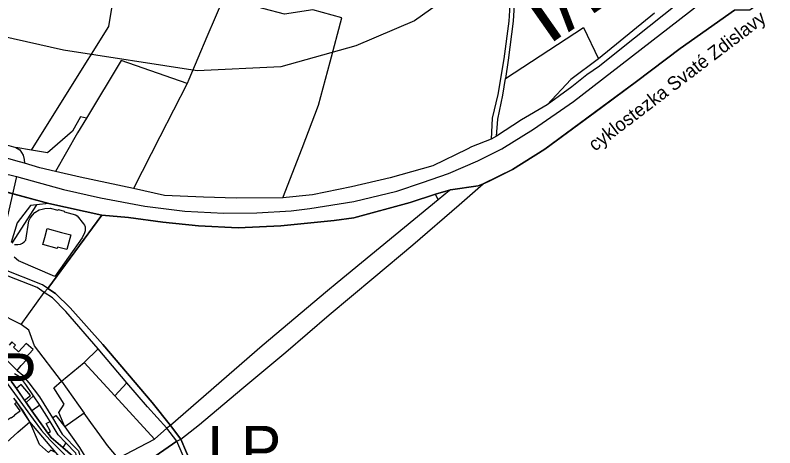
# Model space of a CAD drawing. Extents: x -706771 to -698463, y -971709 to -967107.
# Drawn here: x -701879 to -701207, y -969372 to -968988 of the extents above; entities that cross this region are included whole.
import ezdxf

# ---------------------------------------------------------------- set-up
doc = ezdxf.new("R2010")
doc.units = 0
for name, color, linetype in [('_hranice krajinny raz ochrana chrakteru zástavby KR2', 7, 'Continuous'), ('_KRAJINNY CELEK', 7, 'Continuous'), ('_KRAJINNY OKRSEK', 7, 'Continuous'), ('KN_Hranice_parcel', 7, 'Continuous'), ('Komunikace I třídy osy S', 7, 'Continuous'), ('Komunikace III třídy osy S', 7, 'Continuous'), ('Komunikace popis trid a kategorie popis S N', 7, 'Continuous'), ('Koridor uzemni rezervy zeleznicni trat - osa N', 7, 'Continuous'), ('Prvky nelesni zeleně vhodné k zařazení do vyšší ochrany_popis N', 7, 'Continuous'), ('Prvky nelesní zeleně _dominantní prvky solitérní', 7, 'Continuous'), ('Trasy cyklo popis N', 7, 'Continuous'), ('Trasy cykloturistické N', 7, 'Continuous'), ('Trasy cykloturistické S', 7, 'Continuous'), ('Trasy turistické S', 7, 'Continuous')]:
    doc.layers.add(name, color=color, linetype=linetype)

msp = doc.modelspace()

# ---------------------------------------------------------------- linework, layer by layer
at = {"layer": '_hranice krajinny raz ochrana chrakteru zástavby KR2'}
for p, q in [((-701849.34, -969155.36), (-701907.69, -969139.6)), ((-701802.49, -969165.64), (-701849.34, -969155.36)), ((-701850.32, -969230.41), (-701802.49, -969165.64)), ((-701843.4, -969234.95), (-701850.32, -969230.41)), ((-701757.91, -969331.37), (-701801.62, -969280.03)), ((-701741.49, -969351.93), (-701757.91, -969331.37)), ((-701732.44, -969363.94), (-701741.49, -969351.93)), ((-701691.82, -969459.3), (-701732.44, -969363.94))]:
    msp.add_line(p, q, dxfattribs=at)
msp.add_lwpolyline([(-701801.62, -969280.03), (-701830.6, -969247.76), (-701843.4, -969234.95)], dxfattribs=at)
at = {"layer": '_KRAJINNY CELEK'}
for p, q in [((-701410.21, -969107.23), (-701438.74, -969125.05)), ((-701438.74, -969125.05), (-701464.83, -969137.71)), ((-701493.74, -969143), (-701507.04, -969146.86)), ((-701507.04, -969146.86), (-701529.34, -969154.45)), ((-701529.34, -969154.45), (-701579.3, -969167.87)), ((-701850.32, -969230.41), (-701843.4, -969234.95)), ((-701843.4, -969234.95), (-701830.6, -969247.76)), ((-701830.6, -969247.76), (-701801.62, -969280.03)), ((-701801.62, -969280.03), (-701757.91, -969331.37)), ((-701757.91, -969331.37), (-701741.49, -969351.93)), ((-701741.49, -969351.93), (-701732.44, -969363.94)), ((-701732.44, -969363.94), (-701691.82, -969459.3))]:
    msp.add_line(p, q, dxfattribs=at)
for points in [[(-701438.74, -969125.05), (-701410.21, -969107.23), (-701329.09, -969047.29), (-701290.25, -969018.1), (-701242.42, -968984.02), (-701228.7, -968983.67), (-701152.68, -968925.93), (-701062.83, -968856.76), (-701034.31, -968835.32), (-700968.07, -968795.14), (-700866.46, -968735.36), (-700819.27, -968707.39), (-700809.62, -968702.94)], [(-701228.7, -968983.67), (-701242.42, -968984.02), (-701290.25, -969018.1)], [(-701290.25, -969018.1), (-701329.09, -969047.29), (-701410.21, -969107.23)], [(-701850.32, -969230.41), (-701802.49, -969165.64), (-701778.72, -969167.57), (-701748.57, -969171.91), (-701716.87, -969174.94), (-701681.68, -969176.94), (-701643.83, -969175.03), (-701596.73, -969170.18), (-701579.3, -969167.87), (-701529.34, -969154.45), (-701507.04, -969146.86), (-701493.74, -969143), (-701469.25, -969139.46), (-701464.83, -969137.71), (-701438.74, -969125.05)], [(-701464.83, -969137.71), (-701469.25, -969139.46), (-701493.74, -969143)], [(-701716.87, -969174.94), (-701748.57, -969171.91), (-701778.72, -969167.57), (-701802.49, -969165.64), (-701850.32, -969230.41)], [(-701579.3, -969167.87), (-701596.73, -969170.18), (-701643.83, -969175.03), (-701681.68, -969176.94), (-701716.87, -969174.94)], [(-701691.82, -969459.3), (-701732.44, -969363.94), (-701741.49, -969351.93), (-701757.91, -969331.37), (-701801.62, -969280.03), (-701830.6, -969247.76), (-701843.4, -969234.95), (-701850.32, -969230.41)]]:
    msp.add_lwpolyline(points, dxfattribs=at)
at = {"layer": '_KRAJINNY OKRSEK'}
for p, q in [((-701290.25, -969018.1), (-701329.09, -969047.29)), ((-701329.09, -969047.29), (-701410.21, -969107.23)), ((-701438.74, -969125.05), (-701410.21, -969107.23)), ((-701410.21, -969107.23), (-701438.74, -969125.05)), ((-701464.83, -969137.71), (-701438.74, -969125.05)), ((-701438.74, -969125.05), (-701464.83, -969137.71)), ((-701507.04, -969146.86), (-701493.74, -969143)), ((-701493.74, -969143), (-701507.04, -969146.86)), ((-701493.74, -969143), (-701469.25, -969139.46)), ((-701469.25, -969139.46), (-701493.74, -969143)), ((-701469.25, -969139.46), (-701464.83, -969137.71)), ((-701464.83, -969137.71), (-701469.25, -969139.46)), ((-701529.34, -969154.45), (-701507.04, -969146.86)), ((-701507.04, -969146.86), (-701529.34, -969154.45)), ((-701529.34, -969154.45), (-701579.3, -969167.87)), ((-701802.49, -969165.64), (-701850.32, -969230.41)), ((-701850.32, -969230.41), (-701802.49, -969165.64)), ((-701850.32, -969230.41), (-701843.4, -969234.95)), ((-701843.4, -969234.95), (-701850.32, -969230.41)), ((-701801.62, -969280.03), (-701757.91, -969331.37)), ((-701757.91, -969331.37), (-701801.62, -969280.03)), ((-701757.91, -969331.37), (-701741.49, -969351.93)), ((-701741.49, -969351.93), (-701757.91, -969331.37)), ((-701741.49, -969351.93), (-701732.44, -969363.94)), ((-701732.44, -969363.94), (-701741.49, -969351.93)), ((-701732.44, -969363.94), (-701691.82, -969459.3)), ((-701691.82, -969459.3), (-701732.44, -969363.94))]:
    msp.add_line(p, q, dxfattribs=at)
for points in [[(-701290.25, -969018.1), (-701242.42, -968984.02), (-701228.7, -968983.67), (-701152.68, -968925.93)], [(-701228.7, -968983.67), (-701242.42, -968984.02), (-701290.25, -969018.1)], [(-702372.57, -969017.37), (-702327.41, -969029), (-702270.92, -969043.45), (-702200.53, -969061.14), (-702152.82, -969073.6), (-702124.76, -969080.25), (-702083.33, -969089.48), (-702078.54, -969090.62), (-702054.63, -969097.31), (-702050.66, -969098.08), (-702026.91, -969104.4), (-701983.39, -969123.44), (-701955.32, -969129.82), (-701953.31, -969128.2), (-701949.94, -969127.84), (-701933.2, -969133.88), (-701926.94, -969135.13), (-701907.69, -969139.6), (-701849.34, -969155.36), (-701802.49, -969165.64)], [(-701410.21, -969107.23), (-701329.09, -969047.29), (-701290.25, -969018.1)], [(-701802.49, -969165.64), (-701849.34, -969155.36), (-701907.69, -969139.6)], [(-701596.73, -969170.18), (-701579.3, -969167.87), (-701529.34, -969154.45)], [(-701802.49, -969165.64), (-701778.72, -969167.57), (-701748.57, -969171.91), (-701716.87, -969174.94)], [(-701716.87, -969174.94), (-701748.57, -969171.91), (-701778.72, -969167.57), (-701802.49, -969165.64)], [(-701579.3, -969167.87), (-701596.73, -969170.18), (-701643.83, -969175.03)], [(-701716.87, -969174.94), (-701681.68, -969176.94), (-701643.83, -969175.03), (-701596.73, -969170.18)], [(-701643.83, -969175.03), (-701681.68, -969176.94), (-701716.87, -969174.94)], [(-701843.4, -969234.95), (-701830.6, -969247.76), (-701801.62, -969280.03)], [(-701801.62, -969280.03), (-701830.6, -969247.76), (-701843.4, -969234.95)]]:
    msp.add_lwpolyline(points, dxfattribs=at)
at = {"layer": 'KN_Hranice_parcel'}
for p, q in [((-701313.15, -968986.53), (-701362.78, -969027.22)), ((-701452.9, -969095.61), (-701457.68, -969098.23)), ((-701864.64, -969107.96), (-701878.62, -969105.54)), ((-701849.34, -969155.36), (-701905.57, -969140.09)), ((-701507.04, -969146.86), (-701493.74, -969143)), ((-701504.72, -969151.85), (-701507.04, -969146.86)), ((-701860.42, -969156.4), (-701882.03, -969190.42)), ((-701849.34, -969155.36), (-701860.42, -969156.4)), ((-701802.49, -969165.64), (-701849.34, -969155.36)), ((-701850.32, -969230.41), (-701802.49, -969165.64)), ((-701853.36, -969233.93), (-701850.32, -969230.41)), ((-701873.85, -969262.27), (-701853.36, -969233.93)), ((-701873.85, -969262.27), (-701901, -969248.61)), ((-701805.59, -969283.84), (-701818.22, -969295.98)), ((-701780.28, -969314.21), (-701805.59, -969283.84)), ((-701892.82, -969288.08), (-701877.53, -969303.07)), ((-701838.03, -969312.71), (-701818.22, -969295.98)), ((-701818.22, -969295.98), (-701790.94, -969325.73)), ((-701882.6, -969312.69), (-701877.94, -969319.13)), ((-701838.03, -969312.71), (-701818.12, -969340.93)), ((-701780.28, -969314.21), (-701790.94, -969325.73)), ((-701877.94, -969319.13), (-701870.84, -969329.59)), ((-701870.84, -969329.59), (-701869.57, -969331.44)), ((-701862.96, -969325.56), (-701869.57, -969331.44)), ((-701857.38, -969333.86), (-701862.96, -969325.56)), ((-701790.94, -969325.73), (-701755.9, -969363.95)), ((-701869.57, -969331.44), (-701864.41, -969338.95)), ((-701857.38, -969333.86), (-701864.41, -969338.95)), ((-701864.41, -969338.95), (-701850.36, -969358.69)), ((-701818.12, -969340.93), (-701835.14, -969353)), ((-701755.9, -969363.95), (-701744.84, -969354.31)), ((-701741.49, -969351.93), (-701744.84, -969354.31)), ((-701736.09, -969365.64), (-701744.84, -969354.31)), ((-701787.98, -969380.88), (-701755.9, -969363.95)), ((-701736.09, -969365.64), (-701732.44, -969363.94)), ((-701834.22, -969367.32), (-701837.05, -969371.22)), ((-701736.09, -969365.64), (-701755.24, -969379.17)), ((-701725.43, -969390), (-701736.09, -969365.64))]:
    msp.add_line(p, q, dxfattribs=at)
for points in [[(-700921.77, -968688.04), (-700937.17, -968696.63), (-700980.28, -968723.35), (-701004.83, -968742.42), (-701036.84, -968767.31), (-701073.35, -968796.82), (-701112.91, -968830.3), (-701147.07, -968859.01), (-701170.79, -968881.91), (-701217.18, -968918.15), (-701278.89, -968967.12), (-701343.78, -969019.23), (-701361.79, -969033.5), (-701372.92, -969041.41), (-701386.45, -969051.99), (-701408.01, -969067.71)], [(-701464.83, -969137.71), (-701459.95, -969135.78), (-701438.74, -969125.05), (-701410.21, -969107.23), (-701360.12, -969070.31), (-701329.09, -969047.29), (-701290.25, -969018.1), (-701242.42, -968984.02), (-701228.7, -968983.67), (-701183.96, -968950.9), (-701152.68, -968925.93), (-701107.7, -968891.99), (-701062.83, -968856.76), (-701034.31, -968835.32), (-701018.24, -968825.28), (-700998.24, -968812.95), (-700968.07, -968795.14), (-700944.14, -968780.49), (-700913.64, -968762.81), (-700879.17, -968742.91), (-700866.46, -968735.36)], [(-701431.43, -968850.78), (-701437.38, -968897.95), (-701439.35, -968951.04), (-701441.96, -968993.88), (-701446.56, -969027.25), (-701451.96, -969058.75), (-701456.87, -969079.68), (-701457.68, -969098.23)], [(-701937.91, -968924.22), (-701938.35, -968927.46), (-701939.09, -968933.93), (-701940.42, -968942.26), (-701942.72, -968950.73), (-701946.2, -968960.35), (-701949.09, -968967.46), (-701951.36, -968973.99), (-701953.64, -968980.52), (-701955.94, -968987.11), (-701958.48, -968995.93), (-701958.9, -969006.68), (-701960.15, -969013.95), (-701957.8, -969024.53), (-701953.12, -969039.66), (-701939.02, -969074.81), (-701937.18, -969078.31), (-701931.9, -969086.98), (-701924.7, -969093.31), (-701911.66, -969097.17), (-701886.97, -969103.3), (-701878.62, -969105.54)], [(-701864.64, -969107.96), (-701831.27, -969054.52), (-701796.18, -968998.33), (-701787.95, -968947.73)], [(-701435.49, -968950.02), (-701438.12, -968993.8), (-701442.59, -969028.16), (-701445.16, -969044.47)], [(-701642.18, -969150.25), (-701625.2, -969106.09), (-701610.67, -969068.29), (-701600.4, -969029.83), (-701590.01, -968990.93), (-701615.53, -968983.6), (-701640.8, -968987.68), (-701694.85, -968973.2), (-701709.39, -969007.74), (-701725.27, -969045.48), (-701727, -969048.87)], [(-701445.16, -969044.47), (-701376.12, -968999.24), (-701362.78, -969027.22)], [(-701727, -969048.87), (-701785.41, -969028.64), (-701815.95, -969079.54)], [(-701362.78, -969027.22), (-701387.1, -969045.49), (-701408.01, -969067.71)], [(-701727, -969048.87), (-701751.12, -969096.22), (-701774.47, -969142.05)], [(-701452.9, -969095.61), (-701451.93, -969080.51), (-701447.49, -969059.23), (-701445.16, -969044.47)], [(-701408.01, -969067.71), (-701430.77, -969081.04), (-701452.9, -969095.61)], [(-701815.95, -969079.54), (-701821.19, -969078.54), (-701828.44, -969091.05), (-701850.65, -969110.38), (-701864.64, -969107.96)], [(-701815.95, -969079.54), (-701824.01, -969092.75), (-701843.52, -969126.86)], [(-701871, -969119.62), (-701878.43, -969117.51), (-701933.57, -969101.89)], [(-701457.68, -969098.23), (-701475.01, -969105.06), (-701478.99, -969107.26), (-701509.25, -969121.91), (-701547.06, -969132.41), (-701581.33, -969140.43), (-701616.01, -969147.66), (-701642.18, -969150.25)], [(-701878.62, -969105.54), (-701874.96, -969107.71), (-701872.19, -969112.47), (-701871.19, -969116.37), (-701871, -969119.62)], [(-701843.52, -969126.86), (-701857.44, -969123.55), (-701871, -969119.62)], [(-701774.47, -969142.05), (-701821.65, -969131.78), (-701843.52, -969126.86)], [(-701642.18, -969150.25), (-701683.48, -969150.64), (-701712.55, -969149.57), (-701746.84, -969148.14), (-701774.47, -969142.05)], [(-701732.44, -969363.94), (-701716, -969350.87), (-701678.6, -969319.48), (-701639.64, -969286.88), (-701601.2, -969253.94), (-701561.71, -969220.76), (-701527.04, -969191.82), (-701486.19, -969156.31), (-701464.83, -969137.71)], [(-701493.74, -969143), (-701494.54, -969143.63), (-701504.72, -969151.85)], [(-701464.83, -969137.71), (-701469.25, -969139.46), (-701493.74, -969143)], [(-701507.04, -969146.86), (-701529.34, -969154.45), (-701579.3, -969167.87), (-701596.73, -969170.18), (-701643.83, -969175.03), (-701681.68, -969176.94), (-701716.87, -969174.94), (-701748.57, -969171.91), (-701778.72, -969167.57), (-701802.49, -969165.64)], [(-701860.42, -969156.4), (-701865.51, -969156.88), (-701877.26, -969172.42), (-701882.58, -969189.88)], [(-701504.72, -969151.85), (-701594.05, -969225.46), (-701602.49, -969232.54), (-701660.54, -969281.2), (-701741.49, -969351.93)], [(-701879.66, -969191.61), (-701876.75, -969191.68), (-701874.58, -969191.19), (-701872.6, -969190.26), (-701871.2, -969189.26), (-701869.68, -969187.73), (-701866.99, -969170.47), (-701865.74, -969168.3), (-701863.89, -969165.66), (-701861.65, -969163.1), (-701857.98, -969160.94), (-701855.15, -969160.16), (-701852.75, -969159.69), (-701848.29, -969159.27), (-701841.28, -969161.08), (-701840.8, -969160.6), (-701835.77, -969162.03), (-701835.51, -969162.56), (-701825.79, -969165.27), (-701824.17, -969166.31), (-701818.53, -969173.22), (-701817.8, -969174.54), (-701817.32, -969175.89), (-701817.14, -969177.35), (-701817.27, -969179.36), (-701817.77, -969181.27), (-701819.73, -969185.65), (-701844.07, -969219.99), (-701876.34, -969206.13), (-701880.09, -969202.68)], [(-701850.88, -969177.53), (-701838.28, -969180.83), (-701829.93, -969183.01), (-701833.31, -969195.96), (-701841.58, -969193.79), (-701841.91, -969194.99), (-701854.65, -969191.65), (-701852.92, -969185.36), (-701850.88, -969177.53)], [(-701853.36, -969233.93), (-701859.69, -969229.54), (-701892.11, -969216.98)], [(-701850.32, -969230.41), (-701854.95, -969227.18), (-701890.68, -969213.25)], [(-701741.49, -969351.93), (-701757.91, -969331.37), (-701801.62, -969280.03), (-701830.6, -969247.76), (-701843.4, -969234.95), (-701850.32, -969230.41)], [(-701805.59, -969283.84), (-701834.3, -969250.79), (-701845.98, -969238.82), (-701853.36, -969233.93)], [(-701838.03, -969312.71), (-701862.01, -969281.45), (-701866.93, -969267.48), (-701873.85, -969262.27)], [(-701877.53, -969303.07), (-701873.76, -969298.84), (-701868.68, -969293.15), (-701869.99, -969291.97), (-701863.34, -969284.51), (-701869.41, -969279.1), (-701876.07, -969286.56), (-701880.53, -969282.58), (-701878.86, -969280.71), (-701882.05, -969277.72), (-701884.53, -969280.66)], [(-701877.53, -969303.07), (-701872.32, -969307.33), (-701870.83, -969309.73), (-701867.18, -969314.22), (-701857.72, -969326.37), (-701846.16, -969345.07)], [(-701862.96, -969325.56), (-701869.75, -969315.49), (-701873.3, -969310.74), (-701875.47, -969308.78), (-701879.66, -969306.14)], [(-701870.84, -969329.59), (-701869.78, -969328.68), (-701865.71, -969325.22), (-701873.81, -969315.64), (-701877.94, -969319.13)], [(-701835.14, -969353), (-701840.44, -969340.3), (-701835.64, -969332.9), (-701844.87, -969318.48), (-701838.03, -969312.71)], [(-701744.84, -969354.31), (-701761.9, -969335.23), (-701780.28, -969314.21)], [(-701895.01, -969338.96), (-701892.8, -969342.06), (-701888.23, -969348.44), (-701882.98, -969344.67), (-701882.73, -969345.04), (-701879.44, -969342.69), (-701879.71, -969342.33), (-701874.83, -969338.83), (-701879.4, -969332.45), (-701877.69, -969331.22)], [(-701877.69, -969331.22), (-701877.82, -969331.04), (-701880.37, -969327.67)], [(-701866.19, -969348.55), (-701872.15, -969338.95), (-701877.69, -969331.22)], [(-701848.22, -969348.36), (-701850.98, -969343.6), (-701857.38, -969333.86)], [(-701846.16, -969345.07), (-701843.19, -969343.11), (-701835.14, -969353)], [(-701787.98, -969380.88), (-701797.41, -969369.52), (-701800.26, -969365.57), (-701806.42, -969357.03), (-701812.08, -969349.27), (-701818.12, -969340.93)], [(-701894, -969373.01), (-701876.87, -969357.83), (-701866.19, -969348.55)], [(-701844.19, -969375.53), (-701847.45, -969373.72), (-701849.62, -969375.68), (-701857.56, -969368.8), (-701866.19, -969348.55)], [(-701850.36, -969358.69), (-701847.81, -969357.3), (-701851.65, -969350.22), (-701848.22, -969348.36)], [(-701834.22, -969367.32), (-701841.08, -969360.17), (-701848.22, -969348.36)], [(-701846.16, -969345.07), (-701837.43, -969359.57), (-701823.02, -969374.42), (-701821.83, -969378.46), (-701820.55, -969381.43), (-701818.88, -969383.07)], [(-701835.14, -969353), (-701822.21, -969371.44), (-701814.82, -969383.55)], [(-701850.36, -969358.69), (-701847.18, -969362.37), (-701843.36, -969365.81), (-701837.05, -969371.22)], [(-701572.31, -969634.51), (-701576.12, -969609.1), (-701577.47, -969604.43), (-701577.53, -969603.89), (-701578.24, -969598.49), (-701578.63, -969598.11), (-701578.92, -969587.47), (-701583.19, -969576.91), (-701590.87, -969568.43), (-701599.55, -969563.27), (-701612.37, -969556.92), (-701629.05, -969548.66), (-701649.06, -969537.71), (-701656.12, -969530.16), (-701664.72, -969515.58), (-701673.38, -969497.63), (-701691.82, -969459.3), (-701732.44, -969363.94)], [(-701837.05, -969371.22), (-701825.7, -969380.96), (-701822.99, -969381.99)], [(-701822.99, -969381.99), (-701824.55, -969379.88), (-701825.39, -969376.52), (-701834.22, -969367.32)]]:
    msp.add_lwpolyline(points, dxfattribs=at)
at = {"layer": 'Komunikace I třídy osy S'}
msp.add_lwpolyline([(-702451, -968987.12), (-702427.12, -968991.38), (-702367.42, -969005.48), (-701891.24, -969128.09), (-701877.96, -969131.28), (-701864.2, -969135.12), (-701836.24, -969142.72), (-701803.64, -969150.12), (-701764.5, -969157.5), (-701728.82, -969161.98), (-701694.37, -969163.83), (-701665.1, -969163.65), (-701634.73, -969161.79), (-701618.24, -969159.76), (-701579.35, -969153.46), (-701541.38, -969144.38), (-701518.6, -969136.79), (-701495.64, -969128.64), (-701469.52, -969117.34), (-701448.41, -969106.97), (-701420.12, -969089.38), (-701384.88, -969064.93), (-701085.77, -968833.05)], dxfattribs=at)
at = {"layer": 'Komunikace III třídy osy S'}
for points in [[(-701877.96, -969131.28), (-701886.19, -969167.71)], [(-701899.77, -969296.36), (-701863.36, -969346.16), (-701855.77, -969356.16), (-701848.39, -969364.65), (-701822.11, -969391.05)]]:
    msp.add_lwpolyline(points, dxfattribs=at)
at = {"layer": 'Koridor uzemni rezervy zeleznicni trat - osa N'}
msp.add_lwpolyline([(-700670.52, -968515.75), (-700893.06, -968571.74), (-701041.03, -968647.57), (-701166.81, -968728.96), (-701324.03, -968845.48), (-701410.96, -968912.07), (-701525.64, -968993.45), (-701577.43, -969015.65), (-701644.01, -969034.15), (-701718, -969037.85), (-701836.38, -969019.35), (-702247, -968926.87), (-702439.36, -968886.18), (-702574.39, -968862.13), (-702702.01, -968849.18), (-702786.02, -968846.95), (-702842.65, -968850.23), (-702879.77, -968855.14), (-702924.39, -968864.25), (-702967.67, -968876.1), (-703020.15, -968893.57), (-703051.52, -968908.94), (-703080.69, -968927.25)], dxfattribs=at)
at = {"layer": 'Trasy cykloturistické N'}
msp.add_lwpolyline([(-701809.1, -969398.26), (-701796.72, -969395.96), (-701783.36, -969390.88), (-701762.69, -969383.03), (-701758.38, -969381.39), (-701755.24, -969379.17), (-701736.09, -969365.64), (-701732.44, -969363.94), (-701716, -969350.87), (-701678.6, -969319.48), (-701639.64, -969286.88), (-701601.2, -969253.94), (-701561.71, -969220.76), (-701527.04, -969191.82), (-701486.19, -969156.31), (-701464.83, -969137.71), (-701459.95, -969135.78), (-701438.74, -969125.05), (-701410.21, -969107.23), (-701360.12, -969070.31), (-701329.09, -969047.29), (-701290.25, -969018.1), (-701242.42, -968984.02)], dxfattribs=at)
at = {"layer": 'Trasy cykloturistické S'}
msp.add_lwpolyline([(-701840, -969379.54), (-701866.19, -969348.55), (-701877.69, -969331.22), (-701880.37, -969327.67)], dxfattribs=at)
at = {"layer": 'Trasy turistické S'}
msp.add_lwpolyline([(-701822.99, -969381.99), (-701825.7, -969380.96), (-701837.05, -969371.22), (-701847.18, -969362.37), (-701850.36, -969358.69), (-701864.41, -969338.95), (-701869.57, -969331.44), (-701877.94, -969319.13), (-701882.6, -969312.69)], dxfattribs=at)

# ---------------------------------------------------------------- texts
at = {"layer": 'Komunikace popis trid a kategorie popis S N'}
msp.add_text('I/13  ', height=60, rotation=35.06848, dxfattribs=at).set_placement((-701407.79, -969015.81))
at = {"layer": 'Prvky nelesni zeleně vhodné k zařazení do vyšší ochrany_popis N'}
msp.add_text('LP', height=40, dxfattribs=at).set_placement((-701925.36, -969328.04))
at = {"layer": 'Prvky nelesní zeleně _dominantní prvky solitérní'}
msp.add_text('LP', height=40, dxfattribs=at).set_placement((-701709, -969392.23))
at = {"layer": 'Trasy cyklo popis N'}
msp.add_text('cyklostezka Svaté Zdislavy', height=12, rotation=37.31859, dxfattribs=at).set_placement((-701365.84, -969109.49))

doc.saveas('drawing.dxf')
